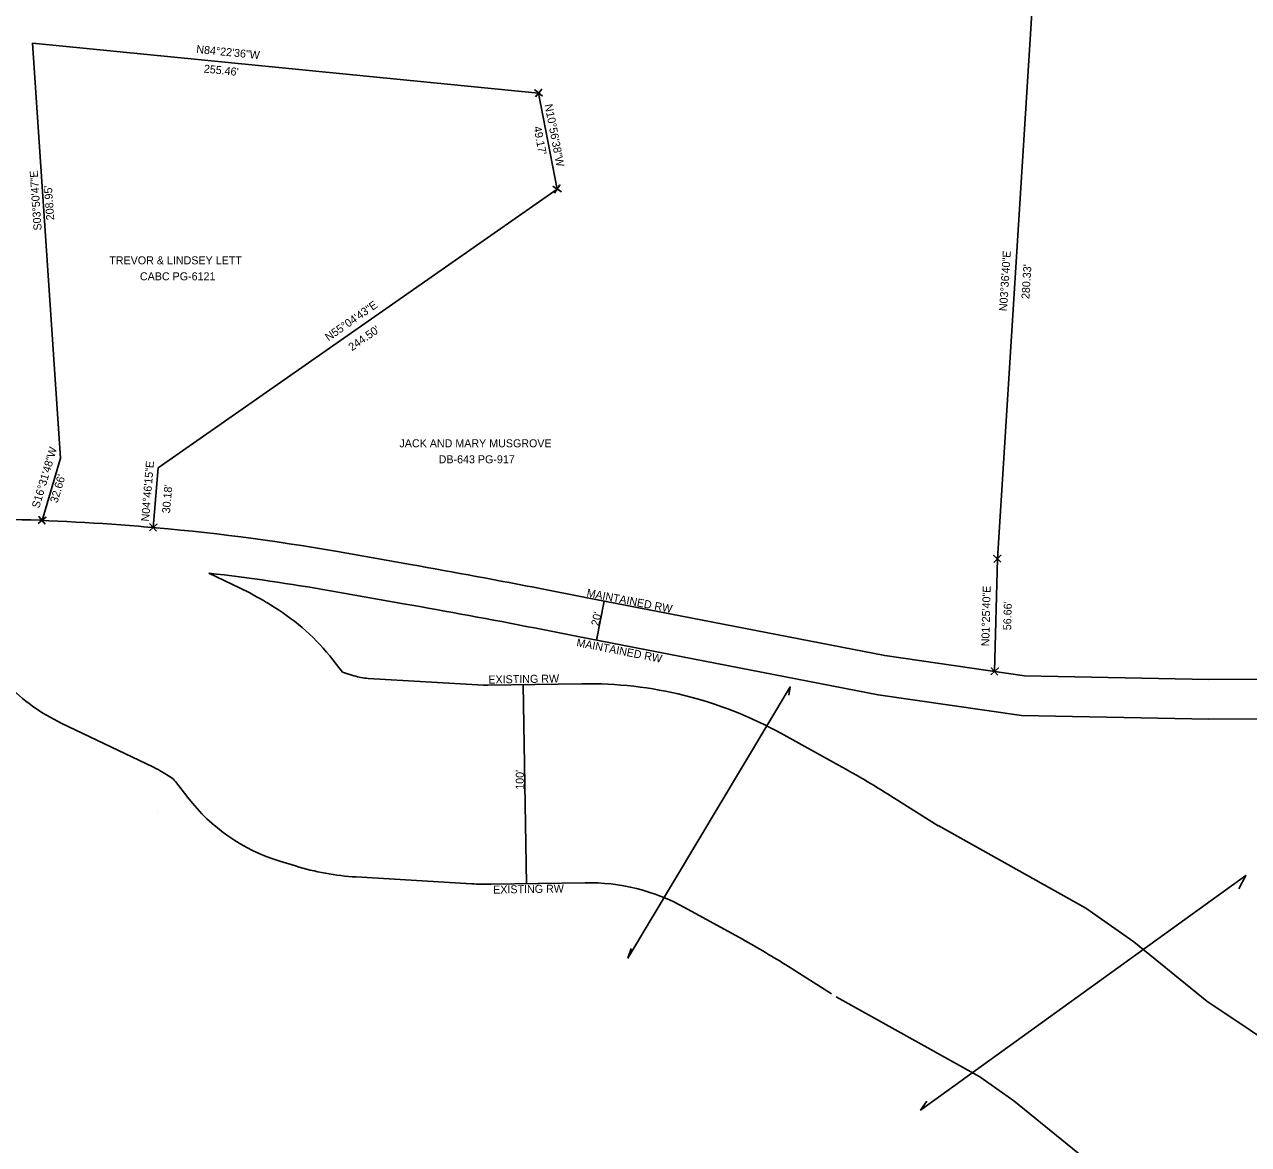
# Model space of a CAD drawing. Extents: x 831731 to 833706, y 722402 to 726085.
# Drawn here: x 832371 to 832986, y 723991 to 724554 of the extents above; entities that cross this region are included whole.
import ezdxf

# ---------------------------------------------------------------- set-up
doc = ezdxf.new("R2010")
doc.units = 0
for name, color, linetype in [('Default', 7, 'Continuous'), ('Exist Property Corner CELL', 7, 'Continuous'), ('Exist Property Line', 7, 'Continuous'), ('Exist Property Same Owner Line CELL', 7, 'Continuous'), ('Exist Property Text', 7, 'Continuous'), ('Exist Right of Way Line', 7, 'Continuous'), ('Exist Right of Way Text', 7, 'Continuous'), ('Exist Right of Way Width CELL', 7, 'Continuous')]:
    doc.layers.add(name, color=color, linetype=linetype)

msp = doc.modelspace()

# ---------------------------------------------------------------- linework, layer by layer
at = {"layer": 'Default'}
for p, q in [((832379.6, 724305.07), (832388.89, 724336.38)), ((832437.96, 724331.58), (832435.45, 724301.5))]:
    msp.add_line(p, q, dxfattribs=at)
at = {"layer": 'Exist Property Corner CELL'}
for p, q in [((832629.1, 724519.82), (832629.1, 724519.82)), ((832638.44, 724471.54), (832638.44, 724471.54)), ((832379.6, 724305.07), (832379.6, 724305.07)), ((832435.45, 724301.5), (832435.45, 724301.5)), ((832859.64, 724285.78), (832859.64, 724285.78)), ((832858.23, 724229.15), (832858.23, 724229.15))]:
    msp.add_line(p, q, dxfattribs=at)
for points in [[(832627.51, 724517.9), (832630.7, 724521.75), (832629.1, 724519.82), (832627.18, 724521.42), (832631.03, 724518.23)], [(832637.07, 724469.45), (832639.8, 724473.64), (832638.44, 724471.54), (832636.35, 724472.91), (832640.53, 724470.18)], [(832377.69, 724303.45), (832381.5, 724306.68), (832379.6, 724305.07), (832377.98, 724306.97), (832381.22, 724303.16)], [(832433.58, 724299.85), (832437.33, 724303.15), (832435.45, 724301.5), (832433.8, 724303.38), (832437.1, 724299.63)], [(832857.9, 724283.99), (832861.37, 724287.58), (832859.64, 724285.78), (832857.84, 724287.52), (832861.43, 724284.05)], [(832856.41, 724227.43), (832860.04, 724230.86), (832858.23, 724229.15), (832856.51, 724230.96), (832859.94, 724227.33)]]:
    msp.add_lwpolyline(points, dxfattribs=at)
at = {"layer": 'Exist Property Line'}
for p, q in [((832859.64, 724285.78), (832877.29, 724565.56)), ((832629.1, 724519.82), (832374.87, 724544.85)), ((832374.87, 724544.85), (832388.89, 724336.38)), ((832638.44, 724471.54), (832629.1, 724519.82)), ((832437.96, 724331.58), (832638.44, 724471.54)), ((832388.89, 724336.38), (832379.6, 724305.07)), ((832435.45, 724301.5), (832437.96, 724331.58)), ((832858.23, 724229.15), (832859.64, 724285.78))]:
    msp.add_line(p, q, dxfattribs=at)
at = {"layer": 'Exist Property Same Owner Line CELL'}
msp.add_line((832437.61, 724158.54), (832437.61, 724158.54), dxfattribs=at)
for points in [[(832754.83, 724217.21), (832755.54, 724221.43), (832674, 724085.15), (832675.53, 724089.99)], [(832980.95, 724119.88), (832984.44, 724126.69), (832821.01, 724008.76), (832824.22, 724013.13)]]:
    msp.add_lwpolyline(points, dxfattribs=at)
at = {"layer": 'Exist Right of Way Line'}
for p, q in [((832428.12, 724302.11), (832430.8, 724301.89)), ((832528.02, 724289.38), (832564.72, 724282.92)), ((832463.42, 724278.58), (832478.74, 724271.25)), ((832630.8, 724270.66), (832651.87, 724266.54)), ((832524.55, 724269.69), (832561.26, 724263.22)), ((832492.46, 724263.78), (832496.29, 724261.43)), ((832626.97, 724251.03), (832648.04, 724246.91)), ((832525.67, 724235.08), (832530.57, 724228.76)), ((832530.57, 724228.76), (832536.33, 724226.98)), ((832543.38, 724225.7), (832601.38, 724222.24)), ((832603.67, 724222.19), (832650.83, 724222.98)), ((832389.24, 724203.23), (832435.56, 724181.05)), ((832750.81, 724198.1), (832779.82, 724182.08)), ((832440.13, 724178.56), (832443.97, 724176.21)), ((832446.64, 724173.81), (832452.89, 724165.74)), ((832808.17, 724165.3), (832829.8, 724151.61)), ((832499, 724133.85), (832506.87, 724131.42)), ((832537.43, 724125.88), (832595.43, 724122.42)), ((832605.33, 724122.21), (832652.49, 724122.99)), ((832702.48, 724110.55), (832731.49, 724094.54)), ((832754.69, 724080.81), (832776.32, 724067.12))]:
    msp.add_line(p, q, dxfattribs=at)
for points in [[(832651.87, 724266.54), (832803.02, 724237.13), (832873.34, 724226.96), (832965.95, 724225.16), (833055.76, 724225.65), (833115.36, 724222.4), (833251.07, 724209.81), (833416.13, 724191.27)], [(832648.05, 724246.91), (832799.67, 724217.41), (832871.71, 724206.99), (832965.81, 724205.16), (833055.27, 724205.65), (833113.9, 724202.45), (833249.03, 724189.91), (833413.9, 724171.4)], [(832829.84, 724151.68), (832904, 724110.25), (832928.25, 724093.21), (832964.9, 724063.53), (833118.37, 723960.76)], [(832778.67, 724065.71), (832850.73, 724025.46), (832867.97, 724013.35), (832905.49, 723982.96)]]:
    msp.add_lwpolyline(points, dxfattribs=at)
for centre, radius, start, end in [((832333.41, 723145.99), 1160, 85.31667, 92.46667), ((832344.25, 723245.43), 1060, 80.01667, 85.31667), ((831938.89, 720727.58), 3610, 78.95, 80.01667), ((832344.25, 723245.43), 1040, 80.01667, 83.42061), ((832413.97, 724135.95), 150, 58.45, 64.41667), ((832438.73, 724167.69), 110, 37.78333, 58.45), ((831938.89, 720727.58), 3590, 78.95, 80.01667), ((832545.17, 724255.65), 30, 252.86688, 266.58606), ((832430.27, 724288.91), 95, 224.13333, 244.41667), ((832603.17, 724252.19), 30, 266.58606, 270.95), ((832654.15, 724023), 200, 61.1, 90.95), ((832413.97, 724135.95), 50, 58.45, 64.41667), ((832514.01, 723700.58), 550, 57.66667, 61.1), ((832438.73, 724167.69), 10, 37.78333, 58.45), ((832526.39, 724222.72), 93, 217.78333, 252.86688), ((832545.17, 724255.65), 130, 252.86688, 266.58606), ((832603.17, 724252.19), 130, 266.58606, 270.95), ((832654.15, 724023), 100, 61.1, 90.95), ((832514.01, 723700.58), 450, 57.66667, 61.1)]:
    msp.add_arc(centre, radius, start, end, dxfattribs=at)
at = {"layer": 'Exist Right of Way Width CELL'}
for p, q in [((832658.23, 724244.92), (832662.06, 724264.55)), ((832622.95, 724122.5), (832621.29, 724222.49))]:
    msp.add_line(p, q, dxfattribs=at)
for points in [[(832662.06, 724264.56), (832662.01, 724264.31), (832661.93, 724264.55)], [(832621.29, 724222.49), (832621.29, 724222.23), (832621.17, 724222.45)]]:
    msp.add_lwpolyline(points, dxfattribs=at)

# ---------------------------------------------------------------- texts
at = {"layer": 'Exist Property Text'}
for s, rotation, p in [('N84°22\'36"W', 354.37659, (832456.97, 724540.01)), ("255.46'", 354.37659, (832460.75, 724530.16)), ('N10°56\'38"W', 280.94396, (832632.09, 724513.96)), ("49.17'", 280.94396, (832626.51, 724502.79)), ('S03°50\'47"E', 93.84651, (832379.4, 724450.89)), ("208.95'", 93.84651, (832385.73, 724456.05)), ('N03°36\'40"E', 86.38902, (832864.48, 724410.12)), ("280.33'", 86.38902, (832875.68, 724416.21)), ('N55°04\'43"E', 34.92139, (832523.55, 724394.99)), ("244.50'", 34.92139, (832535.3, 724390.02)), ('S16°31\'48"W', 73.47, (832378.15, 724310.87)), ('N04°46\'15"E', 85.22917, (832433.33, 724304.41)), ("32.66'", 73.47, (832387.33, 724313.57)), ("30.18'", 85.22917, (832443.86, 724308.49)), ('N01°25\'40"E', 88.57235, (832855.54, 724241.77)), ("56.66'", 88.57235, (832866.54, 724249.84))]:
    msp.add_text(s, height=4.02, rotation=rotation, dxfattribs=at).set_placement(p)
for s, p in [('TREVOR & LINDSEY LETT', (832413.38, 724433.77)), ('CABC PG-6121', (832428.77, 724425.73)), ('JACK AND MARY MUSGROVE', (832559.18, 724341.82)), ('DB-643 PG-917', (832578.88, 724333.78))]:
    msp.add_text(s, height=4.02, dxfattribs=at).set_placement(p)
at = {"layer": 'Exist Right of Way Text'}
for s, rotation, p in [('MAINTAINED RW', 348.98955, (832653.01, 724266.87)), ("20'", 77.99793, (832659.34, 724251.79)), ('MAINTAINED RW', 348.98955, (832647.88, 724241.86)), ('EXISTING RW', 0.95, (832603.88, 724223.06)), ("100'", 89.85135, (832621.63, 724169.68)), ('EXISTING RW', 0.9569, (832606.29, 724117.5))]:
    msp.add_text(s, height=4.02, rotation=rotation, dxfattribs=at).set_placement(p)

doc.saveas('drawing.dxf')
